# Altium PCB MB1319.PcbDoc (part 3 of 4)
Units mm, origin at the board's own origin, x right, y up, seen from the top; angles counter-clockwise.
Board outline 70 x 82.5 mm, 2 copper layers (Top Layer, Bottom Layer), stack 1.571 mm thick; 252 components, 179 nets, 814 pads, 1000 vias.
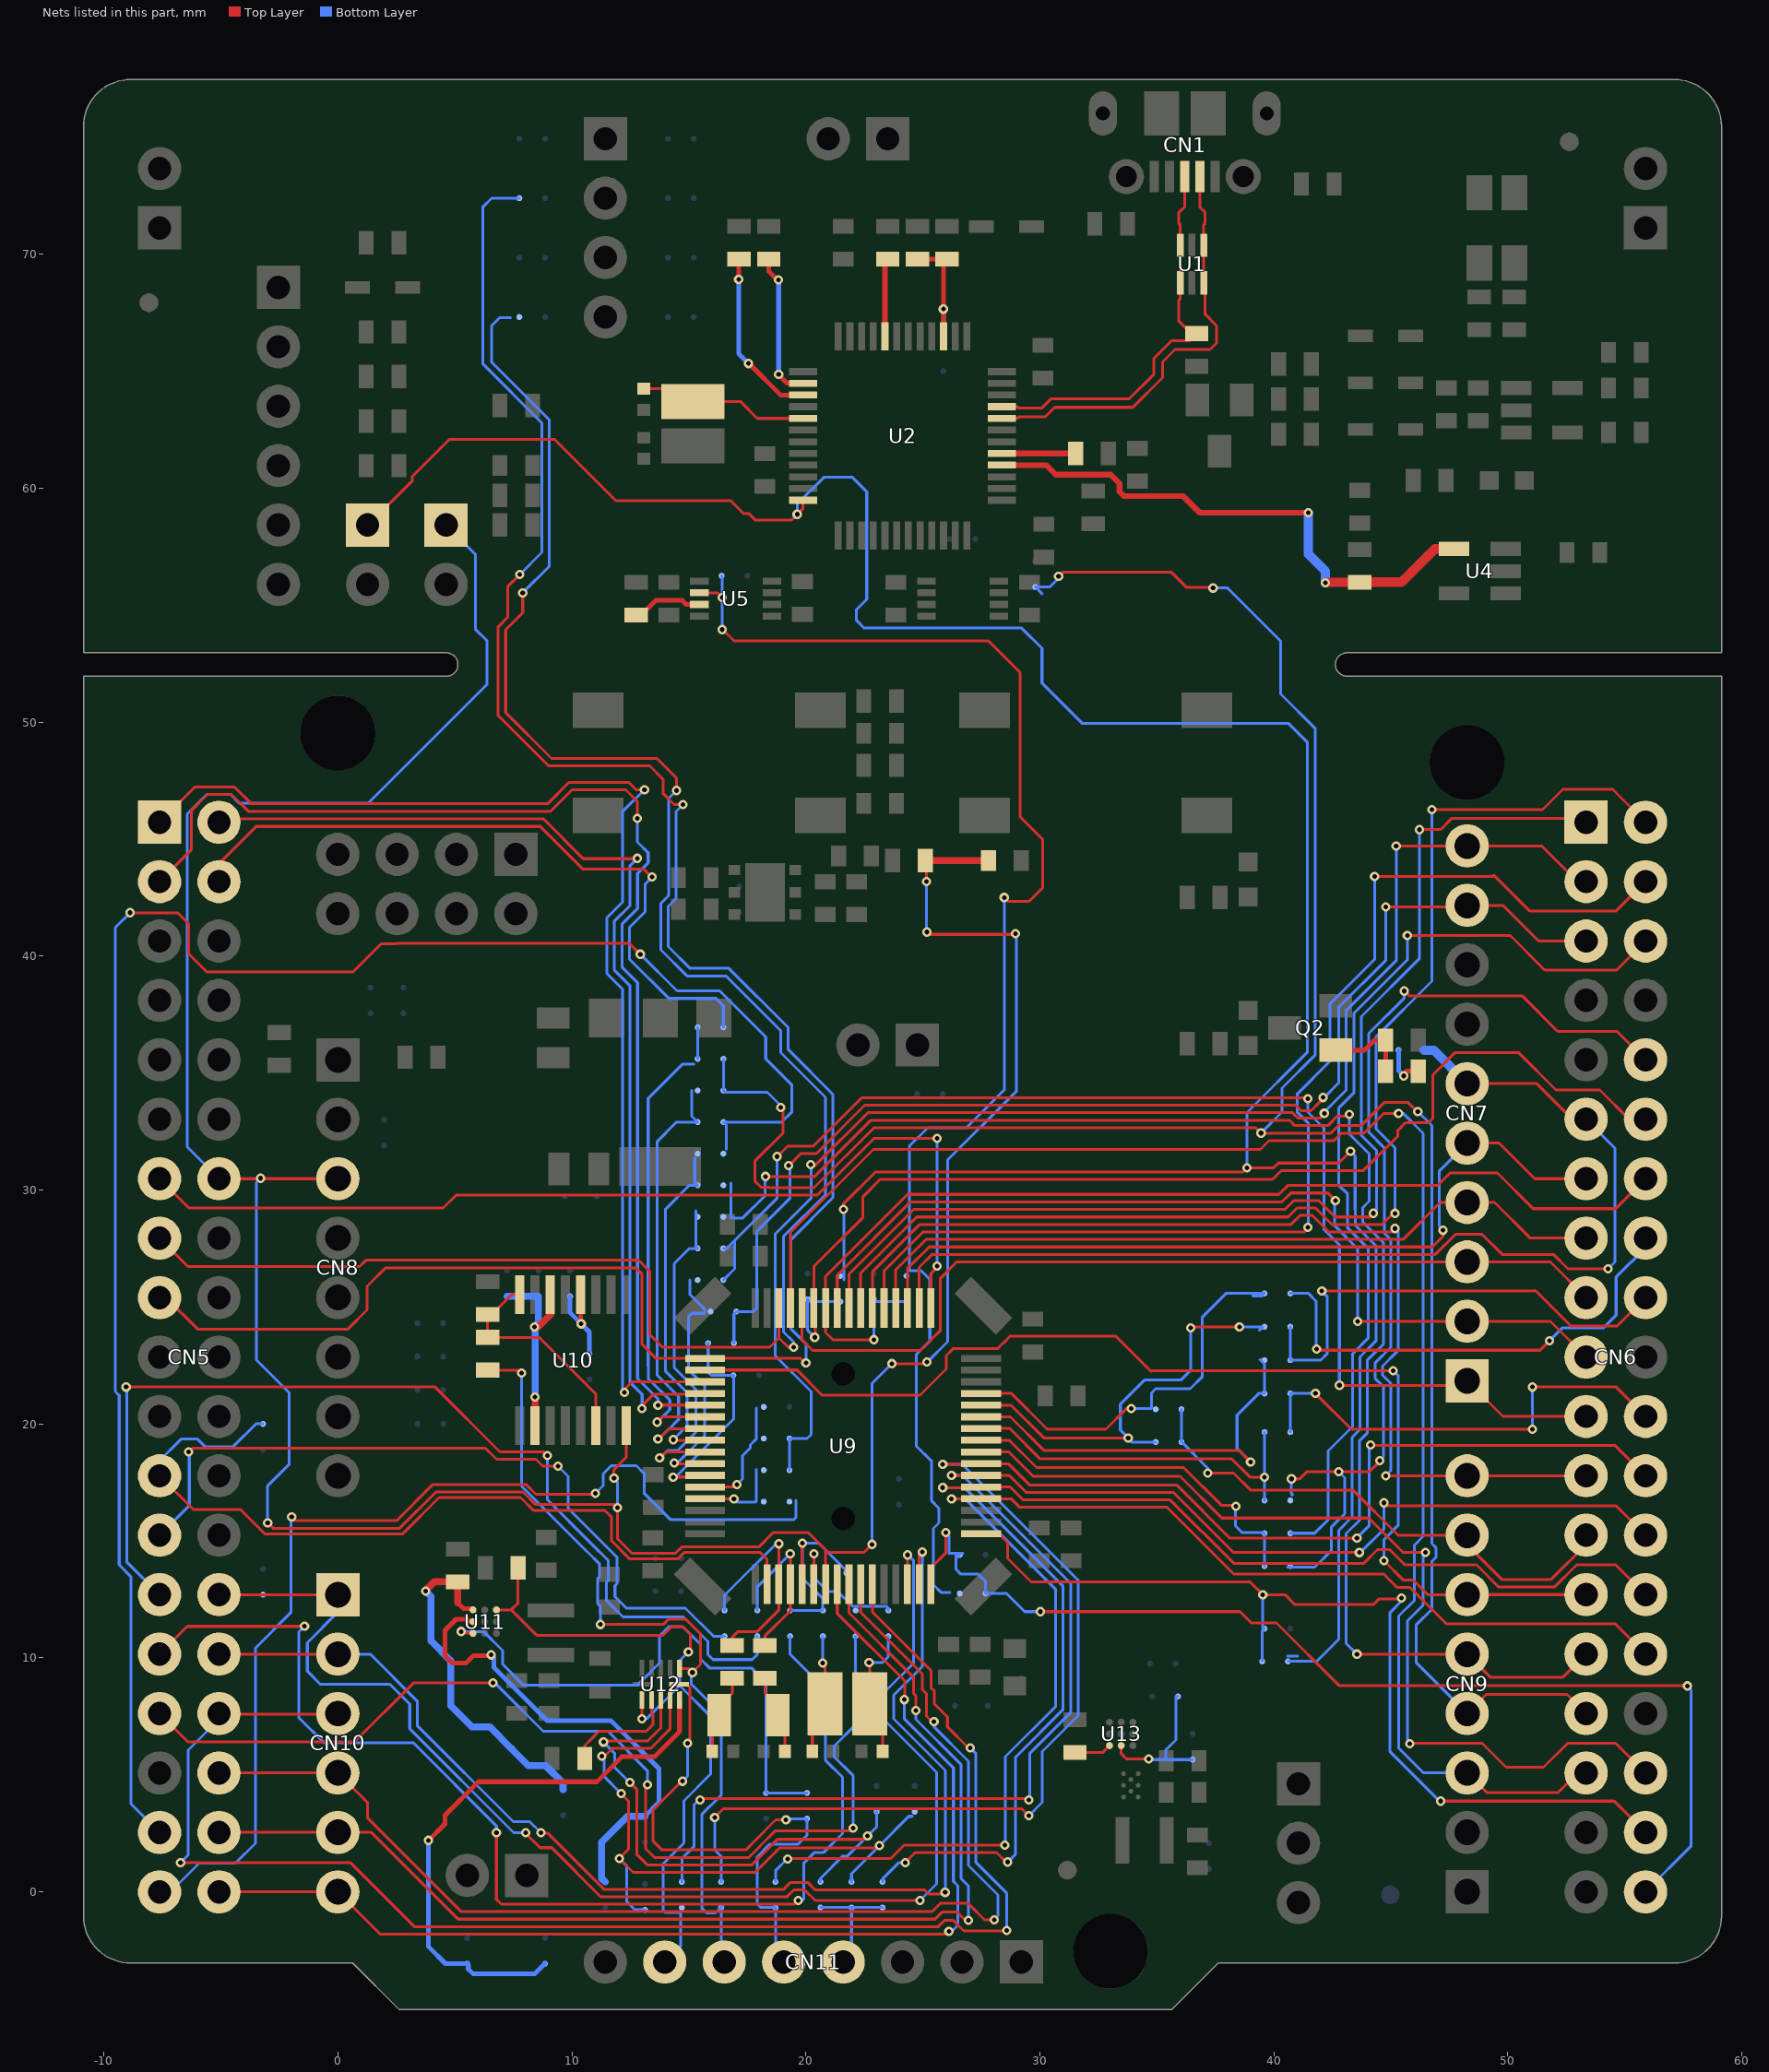
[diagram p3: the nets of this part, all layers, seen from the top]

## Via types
v1: diameter 0.4, hole 0.2, Top Layer to Bottom Layer, tented both sides, 802 vias
v2: diameter 0.6, hole 0.3, Top Layer to Bottom Layer, tented both sides, 198 vias

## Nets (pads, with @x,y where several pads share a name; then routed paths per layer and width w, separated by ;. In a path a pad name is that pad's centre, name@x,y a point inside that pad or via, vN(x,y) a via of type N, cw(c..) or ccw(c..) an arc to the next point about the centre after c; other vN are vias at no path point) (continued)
NetQ2_1: Q2.1 R33.2 R36.2 | length 3.6
  Top Layer w0.2: Q2.1@42.65,35.975 43.875,35.975 44.3,36.4 R33.2@44.775,36.4 R36.2@44.775,35.075
NetR3_2: R3.2 U2.3 | length 7.6
  Top Layer w0.2: v1(17.125,68.925) 17.125,69.765 R3.2@17.145,69.785 ; v1(17.55,65.325) 17.55,65.35 18.92,63.98 U2.3@19.88,63.98
  Bottom Layer w0.2: v1(17.125,68.925) 17.125,65.75 v1(17.55,65.325)
NetR4_2: R4.2 U2.2 | length 6.4
  Top Layer w0.2: R4.2@18.415,69.785 18.415,69.262 18.8,68.877 v1(18.826,68.903) ; v1(18.836,64.864) 18.836,64.85 19.206,64.48 U2.2@19.88,64.48
  Bottom Layer w0.2: v1(18.826,68.903) 18.826,68.929 18.836,68.939 v1(18.836,64.864)
NetR5_2: R5.2 U2.44 | length 3.4
  Top Layer w0.25: U2.44@23.38,66.48 23.38,69.67 R5.2@23.495,69.785
NetR6_1: R6.1 R7.2 SB9.2 U2.39 | length 6.2
  Top Layer w0.2: R6.1@24.765,69.785 R7.2@26.035,69.785 25.875,69.625 v1(25.875,67.65) 25.88,67.645 U2.39@25.88,66.48
  Bottom Layer w0.2: SB9.2@25.875,66.1 v1(25.875,67.65)
NetR19_1: R19.1 U2.29 | length 3.1
  Top Layer w0.25: U2.29@28.38,61.48 31.52,61.48 R19.1@31.525,61.475
NetR26_1: R26.1 U5.7 | length 3
  Top Layer w0.2: R26.1@12.75,54.575 12.961,54.575 13.581,55.195 14.719,55.195 14.889,55.025 U5.7@15.45,55.025
NetR36_1: R36.1 SB17.2 | length 1.9
  Top Layer w0.2: v1(45.55,34.875) 45.55,34.95 45.675,35.075 R36.1@46.175,35.075
  Bottom Layer w0.2: SB17.2@45.325,35.975 45.325,35.1 v1(45.55,34.875)
NetR37_2: R37.2 R38.1 U10.6 U10.16 | length 9.7
  Top Layer w0.12: U10.16@7.775,25.525 7.425,25.525 6.575,24.675 R37.2@6.4,24.675 R38.1@6.4,23.7 6.41,23.69 8.61,23.69 11.025,21.275 U10.6@11.025,19.925
NetR39_2: R39.2 SB83.2 U11.C3 | length 15
  Top Layer w0.2: 5.125,12.35 5.375,12.1 5.725,12.1 U11.C3@5.775,12.05
  Top Layer w0.3: v1(3.75,12.851) 3.75,12.875 4.125,13.25 R39.2@5.125,13.25 5.125,12.35
  Bottom Layer w0.3: v1(3.75,12.851) 3.975,12.626 3.975,10.725 4.825,9.875 4.825,7.95 5.725,7.05 6.495,7.05 7.434,6.111 7.434,6.109 8.143,5.4 8.875,5.4 9.625,4.65 SB83.2@9.625,4.375
NetR41_1: R41.1 SB71.2 U9.4 | length 7.4
  Top Layer w0.12: R41.1@18.25,10.525 18.25,10.925 19.34,12.015 U9.4@19.34,13.15 19.34,14.44 v1(19.33,14.45)
  Bottom Layer w0.12: SB71.2@17.925,12.025 17.925,13.045 v1(19.33,14.45)
NetR42_1: R42.1 SB72.2 U9.3 | length 9.5
  Top Layer w0.12: R42.1@16.85,10.525 16.85,10.874 17.101,11.125 17.925,11.125 18.84,12.04 U9.3@18.84,13.15 18.84,14.865 v1(18.85,14.875)
  Bottom Layer w0.12: SB72.2@16.525,12.025 16.525,12.675 18.725,14.875 v1(18.85,14.875)
NetR43_1: R43.1 U13.C3 | length 1.6
  Top Layer w0.12: R43.1@31.5,5.95 32.675,5.95 U13.C3@32.975,6.25
NetR44_2: R44.2 U12.8 | length 4.9
  Top Layer w0.12: R44.2@10.55,5.7 10.55,6.25 10.891,6.591 11.16,6.86 13.185,6.86 13.46,7.135 13.46,7.591 13.4,7.651 U12.8@13.4,8.2
NetSB16_1: SB16.1 SB18.1 U9.54 | length 20.5
  Top Layer w0.127: v1(13.65,20.075) 13.875,20.3 U9.54@15.69,20.3
  Bottom Layer w0.12: 13.262,22.475 13.262,21.941 13.775,21.427 ; SB18.1@15.375,35.6 SB16.1@15.375,36.95
  Bottom Layer w0.127: 13.262,22.475 13.262,33.912 14.725,35.375 15.225,35.375 ; v1(13.65,20.075) 14.186,20.611 14.186,21.016 13.775,21.427
NetSB19_1: SB19.1 SB22.1 U9.55 | length 19.2
  Top Layer w0.12: v1(13.675,19.35) 13.704,19.35 14.139,19.785 15.675,19.785 U9.55@15.69,19.8
  Bottom Layer w0.12: v1(13.675,19.35) 13.704,19.35 14.139,19.785 14.155,19.785 14.56,20.19 14.56,21.17 13.635,22.095 13.635,32.06 14.475,32.9 SB22.1@15.375,32.9 15.125,33.15 15.125,34.25
NetSB23_1: SB23.1 SB26.1 U9.56 | length 14.9
  Top Layer w0.12: v1(14.33,19.325) 14.355,19.3 U9.56@15.69,19.3
  Bottom Layer w0.12: v1(14.33,19.325) 14.93,19.925 14.93,21.324 14.005,22.248 14.005,29.18 15.025,30.2 SB26.1@15.375,30.2 15.25,30.325 15.25,31.375
NetSB27_1: SB27.1 SB28.1 U9.57 | length 14.6
  Top Layer w0.12: v1(13.751,18.551) 13.751,18.501 14.05,18.8 U9.57@15.69,18.8
  Bottom Layer w0.12: v1(13.751,18.551) 13.75,18.525 14.09,18.865 14.521,18.865 15.3,19.644 15.3,21.477 14.375,22.402 14.375,26.85 15.025,27.5 SB28.1@15.375,27.5 15.3,27.575 15.3,29.1
NetSB29_2: SB29.2 SB42.2 U10.12 | length 4.1
  Top Layer w0.127: v1@10.375,24.35 10.45,24.275 v1(10.4,24.275)
  Top Layer w0.2: v1@10.375,24.35 U10.12@10.375,25.525
  Bottom Layer w0.2: SB29.2@9.925,25.45 9.925,24.75 v1(10.4,24.275) 10.75,23.925 SB42.2@10.75,23
NetSB30_2: SB30.2 SB31.2 U10.2 U10.14 | length 8.7
  Top Layer w0.3: v1(8.4,24.15) 8.57,24.15 9.1,24.68 9.1,25.5 U10.14@9.075,25.525 ; U10.2@8.425,19.925 v1(8.425,21.15)
  Bottom Layer w0.3: SB31.2@7.225,25.45 SB30.2@8.575,25.45 8.575,24.325 v1(8.4,24.15) 8.425,24.125 v1(8.425,21.15)
NetSB36_1: SB36.1 SB38.1 U9.58 | length 11
  Top Layer w0.12: v1(14.376,18.326) 14.35,18.3 14.35,18.275 14.375,18.3 U9.58@15.69,18.3
  Bottom Layer w0.12: v1(14.376,18.326) 14.505,18.326 15.67,19.491 15.67,21.63 14.975,22.325 14.975,24.575 15.125,24.725 15.675,24.725 15.675,24.9 15.05,25.525 15.05,26.15
NetSB37_1: SB37.1 SB49.1 U9.29 | length 17.6
  Top Layer w0.12: U9.29@27.49,21.3 28.786,21.3 30.316,19.77 32.82,19.77 33.7,20.65 v1(33.9,20.65)
  Bottom Layer w0.12: v1(33.9,20.65) 34.775,20.65 34.775,21.325 34.95,21.5 36.425,21.5 36.945,22.02 36.945,24.57 37.95,25.575 SB37.1@39.6,25.575 39.5,25.475 39.1,25.475
NetSB40_1: SB40.1 SB54.1 U9.28 | length 18.5
  Top Layer w0.12: U9.28@27.49,20.8 28.763,20.8 30.163,19.4 v1(33.775,19.4) ; v1(36.45,24.1) 36.501,24.151 v1(38.527,24.151)
  Bottom Layer w0.12: SB54.1@34.95,19.225 33.925,19.225 33.75,19.4 v1(33.775,19.4) 33.44,19.735 33.44,20.841 34.469,21.87 36.02,21.87 36.45,22.3 v1(36.45,24.1) ; v1(38.527,24.151) 38.526,24.15 39.525,24.15 39.375,24
NetSB41_2: SB41.2 SB45.1 U9.59 | length 9.3
  Top Layer w0.127: v1(14.326,17.726) 15.616,17.726 U9.59@15.69,17.8
  Bottom Layer w0.127: v1(14.326,17.726) 14.433,17.726 16.916,20.209 16.916,22.059 SB45.1@16.9,22.075 15.95,22.075 15.825,22.2 SB41.2@15.825,23.45
NetSB44_1: SB44.1 SB47.1 U9.27 | length 17.6
  Top Layer w0.12: U9.27@27.49,20.3 28.74,20.3 30.17,18.87 38.505,18.87 v1(39,18.375)
  Bottom Layer w0.12: v1(39,18.375) 38.425,18.95 38.425,20.375 39.35,21.3 SB47.1@39.6,21.3 39.6,22.55 39.4,22.75
NetSB48_1: SB48.1 SB53.1 U9.60 | length 5
  Top Layer w0.12: U9.60@15.69,17.3 16.95,17.3 v1(17.051,17.401)
  Bottom Layer w0.12: v1(17.051,17.401) 17.29,17.64 17.29,18.64 17.625,18.975 17.625,19.1 17.875,19.35 17.875,20.675
NetSB52_1: SB52.1 SB57.1 U9.26 | length 15.9
  Top Layer w0.12: U9.26@27.49,19.8 28.716,19.8 30.016,18.5 38.2,18.5 38.975,17.725 v1(39.6,17.725)
  Bottom Layer w0.12: SB57.1@39.6,16.725 v1(39.6,17.725) SB52.1@39.6,19.65
NetSB55_1: SB55.1 SB58.1 U9.61 | length 3.6
  Top Layer w0.12: U9.61@15.69,16.8 v1(16.925,16.8)
  Bottom Layer w0.12: v1(16.925,16.8) 17.075,16.65 17.85,16.65 17.875,16.675 17.875,18.05
NetSB59_1: SB59.1 SB63.1 U9.25 | length 15.7
  Top Layer w0.12: U9.25@27.49,19.3 28.693,19.3 29.863,18.13 36.145,18.13 37.75,16.525 38.375,16.525 38.377,16.523 v1(38.377,16.476)
  Bottom Layer w0.12: v1(38.377,16.476) 38.351,16.476 38.351,15.649 38.65,15.35 39.575,15.35 SB59.1@39.6,15.325 SB63.1@39.6,13.925
NetSB64_2: SB64.2 SB69.2 SB70.2 U9.5 | length 8.9
  Top Layer w0.12: U9.5@19.84,13.15 19.84,14.89 v1(19.85,14.9)
  Bottom Layer w0.12: SB70.2@19.325,12.025 SB69.2@20.725,12.025 20.725,12.527 19.85,13.402 v1(19.85,14.9) 19.86,14.91 20.541,14.91 21.725,13.726 SB64.2@21.725,13.625
NetSB67_2: SB67.2 SB68.2 U9.6 | length 6.1
  Top Layer w0.12: U9.6@20.34,13.15 20.34,14.44 v1(20.35,14.45)
  Bottom Layer w0.12: v1(20.35,14.45) 20.35,13.425 20.94,12.835 21.365,12.835 22,12.2 23.45,12.2 23.525,12.125 SB67.2@23.525,12.025
NetSB79_2: SB79.2 SB80.2 U13.B3 | length 6.4
  Top Layer w0.12: U13.B3@33.475,6.25 33.475,5.9 33.7,5.675 v1(34.65,5.675)
  Bottom Layer w0.12: v1@34.675,5.675 34.7,5.65 35.375,5.65 ; SB79.2@35.9,8.35 35.815,8.35 35.815,6.489 35.541,6.215 35.375,6.05 35.375,5.65 ; SB80.2@36.525,5.65 35.375,5.65
NetSB81_2: SB81.2 SB91.2 U12.9 | length 24
  Top Layer w0.12: v1(11.351,6.4) 11.4,6.45 13.242,6.45 13.8,7.007 U12.9@13.8,8.2 ; v1(12.475,4.674) 12.785,4.364 12.785,1.59 13.225,1.15 17.697,1.15 18.4,1.853 18.4,1.859 18.781,2.24 22.49,2.24 v1(22.638,2.388)
  Bottom Layer w0.12: v1(11.351,6.4) 11.825,5.926 11.825,5.324 v1(12.475,4.674) ; SB91.2@20.625,0.425 20.625,0.575 21.575,1.525 21.775,1.525 v1(22.638,2.388) 23.025,2.775 SB81.2@23.025,3.425
NetSB82_2: SB82.2 SB90.2 SB94.2 U12.10 | length 28.4
  Top Layer w0.12: v1(11.276,5.8) 11.401,5.8 11.73,6.13 13.375,6.13 14.19,6.945 U12.10@14.19,8.2 ; v1(12.101,4.2) 12.415,3.886 12.415,1.815 v1(12.025,1.425) 12.62,0.83 17.83,0.83 18.72,1.72 18.72,1.727 18.863,1.87 23.044,1.87 v1(23.149,1.975)
  Bottom Layer w0.12: v1(11.276,5.8) 11.385,5.691 11.385,4.916 v1(12.101,4.2) ; v1(12.025,1.425) 12.35,1.1 12.35,-0.425 12.7,-0.775 SB94.2@13.125,-0.775 ; SB90.2@21.95,0.425 21.95,0.776 v1(23.149,1.975) 24.399,3.225 24.55,3.225
NetSB84_2: SB84.2 SB85.2 U11.A3 | length 24.4
  Top Layer w0.12: v1(5.275,11.125) 5.35,11.05 U11.A3@5.775,11.05
  Bottom Layer w0.12: v1(5.275,11.125) 6.228,11.125 7.04,10.313 7.04,9.726 7.941,8.825 12.791,8.825 13.74,9.774 13.74,10.932 14.143,11.335 14.732,11.335 15.495,10.572 15.495,9.955 15.895,9.555 17.695,9.555 18.3,8.95 SB85.2@18.3,4.225 SB84.2@20.05,4.225
NetSB86_2: SB86.2 SB95.2 U11.B3 | length 20.6
  Top Layer w0.2: U11.B3@5.775,11.55 5.639,11.55 5.539,11.65 5.05,11.65 4.575,11.175 4.575,10.085 4.875,9.785 5.484,9.785 5.799,10.1 6.525,10.1 v1(6.55,10.125)
  Bottom Layer w0.2: v1(6.55,10.125) 6.675,10 6.675,9.582 8.937,7.32 11.665,7.32 13.725,5.261 13.725,3.825 SB86.2@13.125,3.225
  Bottom Layer w0.3: SB95.2@11.425,0.425 11.275,0.575 11.275,2.125 12.375,3.225 SB86.2@13.125,3.225
NetSB96_2: SB96.2 SB97.2 U12.11 | length 24.5
  Top Layer w0.2: v1(3.874,2.199) 4.575,2.899 4.575,3.275 6.004,4.704 11.067,4.704 12.133,5.77 13.524,5.77 14.6,6.846 U12.11@14.6,8.2
  Bottom Layer w0.2: v1(3.874,2.199) 3.874,-2.349 4.6,-3.075 SB96.2@5.525,-3.075 5.575,-3.125 5.575,-3.3 5.775,-3.5 8.425,-3.5 SB97.2@8.85,-3.075
NRST: C23.2 CN5.14 CN8.3 JP4.1 R31.1 U9.7 U10.8 | length 133.8
  Top Layer w0.12: CN5.14@-5.08,30.48 v1@-3.32,30.48 ; v1(-3.3,30.5) v1@-3.32,30.48 ; v1(-3,15.775) -2.765,15.54 2.64,15.54 4.19,17.09 7.91,17.09 8.435,16.565 11.815,16.565 v1@11.95,16.43 ; CN8.3@0,30.48 v1@-3.32,30.48 ; v1(11.8,17.675) 11.8,18.05 12.325,18.575 U10.8@12.325,19.925 ; v1@11.94,16.51 11.94,15.099 12.574,14.465 14.426,14.465 14.701,14.74 17.99,14.74 18.61,15.36 20.091,15.36 20.84,14.611 ; U9.7@20.84,13.15 20.84,14.611 ; v1(22.825,14.85) 22.49,14.515 20.936,14.515 20.84,14.611 ; v1(23.675,22.575) 25.1,22.575 v1(25.176,22.651) ; R31.1@25.1,44.075 25.15,44.025 v1(25.15,43.175) ; v1(25.175,41.025) 25.275,40.925 28.95,40.925 v1(28.95,40.95)
  Top Layer w0.3: R31.1@25.1,44.075 C23.2@27.8,44.075
  Bottom Layer w0.12: CN5.14@-5.08,30.48 -6.435,31.835 -6.435,46.065 -5.595,46.905 -4.589,46.905 -4.224,46.54 1.307,46.54 6.38,51.613 6.38,53.47 5.875,53.975 5.875,57.17 JP4.1@4.625,58.42 ; v1(-3.3,30.5) -3.48,30.32 -3.48,22.733 -2.09,21.343 -2.09,18.26 -3,17.35 v1(-3,15.775) ; v1(11.8,17.675) 11.95,17.525 v1(11.95,16.425) ; v1(22.825,14.85) 22.825,21.725 v1(23.675,22.575) ; v1(25.15,43.175) 25.15,41.05 v1(25.175,41.025) ; v1(25.176,22.651) 25.199,22.651 26.061,23.513 26.061,31.286 29,34.225 29,41 v1(28.95,40.95)
OSC32_IN: C45.1 R42.2 X3.1 | length 3.5
  Top Layer w0.12: C45.1@16,6 16,7.25 X3.1@16.3,7.55 16.3,7.925 16.85,8.475 R42.2@16.85,9.125
OSC32_OUT: C46.1 R41.2 X3.2 | length 3.5
  Top Layer w0.12: R41.2@18.25,9.125 18.25,8.525 18.8,7.975 X3.2@18.8,7.55 19.1,7.25 C46.1@19.1,6
OSC_IN: C47.2 SB69.1 X2.2 | length 4.4
  Top Layer w0.12: C47.2@20.275,6 X2.2@20.275,7.475 ; v1(20.725,9.775) 20.825,9.675 X2.2@20.825,8.025
  Bottom Layer w0.12: v1(20.725,9.775) SB69.1@20.725,10.925
OSC_OUT: C48.2 SB67.1 X2.1 | length 5.8
  Top Layer w0.12: v1(22.7,9.8) 22.725,9.775 X2.1@22.725,8.025 23.275,7.475 C48.2@23.275,6
  Bottom Layer w0.12: v1(22.7,9.8) 23.275,9.8 23.525,10.05 SB67.1@23.525,10.925
PA0: CN5.28 CN10.1 SB62.2 U9.14 | length 59.8
  Top Layer w0.12: CN5.28@-5.08,12.7 CN10.1@0,12.7 ; v1(8.024,2.525) 8.024,2.501 8.64,1.885 9.14,1.885 11.235,-0.21 19.216,-0.21 19.216,-0.184 19.485,0.085 19.94,0.085 20.4,-0.375 v1(24.876,-0.375) ; U9.14@24.34,13.15 24.34,14.39 v1(24.35,14.4)
  Bottom Layer w0.12: CN5.28@-5.08,12.7 SB62.2@-3.2,12.7 ; CN10.1@0,12.7 0,11.95 -1.305,10.645 -1.305,9.43 -0.75,8.875 2.218,8.875 3.07,8.023 3.07,6.973 7.518,2.525 v1(8.024,2.525) ; v1(24.35,14.4) 24.605,14.145 24.605,9.781 23.381,8.557 23.381,7.314 25.59,5.105 25.59,0.339 v1(24.876,-0.375)
PA1: CN5.30 CN10.2 U9.15 | length 53.6
  Top Layer w0.12: CN5.30@-5.08,10.16 CN10.2@0,10.16 ; v1(8.675,2.525) 8.7,2.5 8.978,2.5 11.368,0.11 19.058,0.11 19.353,0.405 20.073,0.405 20.393,0.085 25.067,0.085 25.25,-0.099 25.951,-0.099 v1(25.951,-0.025) ; U9.15@24.84,13.15 24.84,14.385 v1(24.975,14.52)
  Bottom Layer w0.12: CN10.2@0,10.16 1.385,10.16 3.39,8.155 3.39,7.105 7.495,3 8.2,3 v1(8.675,2.525) ; v1(24.975,14.52) 24.975,9.628 23.751,8.404 23.751,7.396 25.96,5.187 25.96,-0.016 v1(25.951,-0.025)
PA2: CN6.38 SB60.1 SB66.2 U9.16 | length 48.1
  Top Layer w0.12: U9.16@25.34,13.15 25.34,13.84 25.975,14.475 v1(25.975,15.35) ; v1(30.025,11.975) 38.553,11.975 39.033,11.495 40.11,11.495 42.8,8.805 57.655,8.805 57.675,8.825 v1(57.675,8.8)
  Bottom Layer w0.12: v1(25.975,15.35) 26.125,15.2 26.125,14.475 26.412,14.475 ; 26.475,14.3 SB60.1@26.575,14.4 ; 26.7,14.475 26.412,14.475 ; v1(30.025,11.975) 29.35,11.975 28.575,12.75 SB66.2@27.675,12.75 27.675,13.275 27.375,13.575 26.625,13.575 26.412,13.787 26.412,14.475 ; CN6.38@55.88,0 57.82,1.94 57.82,8.655 v1(57.675,8.8)
PA3: CN6.36 SB73.1 SB75.2 U9.17 | length 41.8
  Top Layer w0.12: U9.17@27.49,15.3 28.25,15.3 28.625,14.925 28.625,14.25 29.625,13.25 38.978,13.25 v1(39.527,12.701) 40.474,12.701 40.9,12.275 44.25,12.275 44.5,12.525 45.45,12.525 v1(45.45,12.551) ; v1(47.125,3.875) 54.545,3.875 CN6.36@55.88,2.54
  Bottom Layer w0.12: SB75.2@39.5,9.85 39.5,11.15 SB73.1@39.6,11.25 39.525,11.325 39.525,12.699 v1(39.527,12.701) ; v1(45.45,12.551) 45.45,12.423 44.965,11.938 44.965,5.986 47.076,3.875 v1(47.125,3.875)
PA4: CN6.30 SB92.2 U9.20 | length 61.1
  Top Layer w0.12: v1(19.226,1.4) 19.251,1.425 23.625,1.425 24.195,1.995 28.496,1.995 v1(28.501,2) ; v1(26.225,16.8) U9.20@27.49,16.8 28.772,16.8 29.142,16.43 35.441,16.43 38.296,13.575 44.7,13.575 45.264,13.011 45.814,13.011 47.375,11.45 54.59,11.45 CN6.30@55.88,10.16
  Bottom Layer w0.12: SB92.2@18.7,0.425 18.7,0.9 19.2,1.4 v1(19.226,1.4) ; v1(26.225,16.8) 26.797,16.8 30.675,12.922 30.675,7.925 28.526,5.776 28.526,1.975 v1(28.501,2)
PA5: CN6.28 SB89.2 U9.21 | length 59
  Top Layer w0.12: v1(24.25,1.25) 24.675,1.675 28.15,1.675 28.575,1.25 28.601,1.25 v1(28.626,1.275) ; v1(25.85,17.275) 27.465,17.275 U9.21@27.49,17.3 28.741,17.3 29.291,16.75 35.573,16.75 38.283,14.04 43.841,14.04 44.426,14.625 44.951,14.625 45.601,13.975 48.661,13.975 49.612,13.023 51.988,13.023 52.939,13.975 54.605,13.975 CN6.28@55.88,12.7
  Bottom Layer w0.12: SB89.2@23.275,0.425 23.275,0.55 23.975,1.25 v1(24.25,1.25) ; v1(25.85,17.275) 26.775,17.275 30.995,13.055 30.995,7.792 28.961,5.759 28.961,1.61 v1(28.626,1.275)
PA6: CN6.26 SB93.2 U9.22 | length 68.2
  Top Layer w0.12: v1(15.476,3.925) 15.526,3.975 29.477,3.975 v1(29.526,3.925) ; v1(26.225,17.8) U9.22@27.49,17.8 28.694,17.8 29.424,17.07 35.706,17.07 38.276,14.5 v1(43.65,14.5) ; v1(44.7,16.625) 44.825,16.5 54.62,16.5 CN6.26@55.88,15.24
  Bottom Layer w0.12: SB93.2@14.7,0.425 14.7,1.425 15.225,1.95 15.225,3.725 15.45,3.95 v1@15.475,3.925 ; v1(26.225,17.8) 26.703,17.8 31.315,13.188 31.315,7.66 29.575,5.92 29.575,3.877 v1(29.526,3.925) ; v1(43.65,14.5) 43.692,14.5 44.7,15.508 v1(44.7,16.625)
PA7: CN6.24 SB88.2 U9.23 | length 70.9
  Top Layer w0.12: v1(16.1,3.175) 16.475,3.55 29.225,3.55 v1(29.525,3.25) ; v1(25.85,18.275) 27.465,18.275 U9.23@27.49,18.3 28.647,18.3 29.557,17.39 35.838,17.39 38.103,15.125 v1(43.55,15.125) ; v1(44.125,19.1) 44.15,19.075 54.585,19.075 CN6.24@55.88,17.78
  Bottom Layer w0.12: v1(16.1,3.175) 16.125,3.2 16.125,3 16.115,2.99 16.115,1.78 16.375,1.52 SB88.2@16.375,0.425 ; v1(25.85,18.275) 26.68,18.275 31.635,13.32 31.635,7.527 30.1,5.992 30.1,3.825 v1(29.525,3.25) ; v1(43.55,15.125) 44.067,15.642 44.067,19.042 v1(44.125,19.1)
PA8: CN6.19 CN7.2 U9.41 | length 40.3
  Top Layer w0.12: U9.41@21.34,24.95 21.34,26.352 24.478,29.49 40.346,29.49 40.726,29.87 42.305,29.87 v1(42.625,29.55) ; v1(43.575,24.375) 43.584,24.384 CN7.2@48.26,24.384 51.816,24.384 CN6.19@53.34,22.86
  Bottom Layer w0.12: v1(42.625,29.55) 42.6,29.525 42.6,28.468 43.575,27.493 v1(43.575,24.375)
PA9: CN6.14 SB34.2 SB35.1 U9.42 | length 45.8
  Top Layer w0.12: v1(22.9,23.6) 21.15,23.6 20.84,23.91 U9.42@20.84,24.95 20.84,26.304 24.346,29.81 40.213,29.81 40.593,30.19 46.99,30.19 47.525,30.725 49.55,30.725 51.075,29.2 54.6,29.2 CN6.14@55.88,30.48
  Bottom Layer w0.12: v1(22.9,23.6) SB35.1@22.9,25.325 23,25.225 SB34.2@24.3,25.225
PA10: CN6.12 SB32.2 SB33.1 U9.43 | length 48.6
  Top Layer w0.12: v1(20.376,23.701) 20.4,23.725 20.4,24.89 U9.43@20.34,24.95 20.34,26.727 22.44,28.827 22.44,29.714 23.176,30.45 39.948,30.45 40.328,30.83 43.827,30.83 45.3,32.303 45.3,32.549 45.623,32.873 46.599,32.873 46.788,33.062 46.788,34.913 47.75,35.875 50.45,35.875 52.05,34.275 53.925,34.275 55.18,33.02 CN6.12@55.88,33.02
  Bottom Layer w0.12: v1@20.325,23.65 v1(20.376,23.701) 20.075,24.002 SB33.1@20.075,25.325 20.175,25.225 SB32.2@21.475,25.225
PA11: CN6.17 CN7.3 U9.44 | length 38.6
  Top Layer w0.12: U9.44@19.84,24.95 19.84,23.587 20.287,23.14 24.89,23.14 25.59,23.84 25.598,23.84 25.75,23.992 25.75,26.225 26.449,26.924 CN7.3@48.26,26.924 51.816,26.924 CN6.17@53.34,25.4
PA12: CN6.33 CN9.3 U9.45 | length 68.6
  Top Layer w0.12: U9.45@19.34,24.95 19.34,28.184 22.886,31.73 39.418,31.73 39.798,32.11 42.567,32.11 42.887,32.43 43.854,32.43 44.699,33.275 v1(45.325,33.275) ; CN9.3@48.26,5.08 49.095,4.245 52.15,4.245 52.985,5.08 CN6.33@53.34,5.08
  Bottom Layer w0.12: v1(45.325,33.275) 45.526,33.275 46.38,32.421 46.38,15.195 46.01,14.825 46.01,12.46 45.335,11.785 45.335,6.139 46.394,5.08 CN9.3@48.26,5.08
PA13: CN5.15 SB8.1 U9.46 | length 89.6
  Top Layer w0.12: CN5.15@-7.62,27.94 -6.405,26.725 0.934,26.725 1.204,26.995 12.858,26.995 13.32,26.533 13.32,23.83 13.875,23.275 18.45,23.275 18.85,23.675 ; v1(7.9,55.525) 7.9,54.672 7.17,53.942 7.17,50.408 9.133,48.445 13.633,48.445 14.475,47.603 v1(14.475,47.075) ; U9.46@18.84,24.95 18.85,24.94 18.85,23.675 ; v1(19.475,23.275) 19.25,23.275 18.85,23.675
  Bottom Layer w0.12: 7.375,67.275 6.9,67.275 6.575,66.95 6.575,65.375 9.04,62.91 9.04,56.665 v1(7.9,55.525) ; v1(14.475,47.075) 14.135,46.735 14.135,42.584 13.8,42.249 13.8,40.268 14.918,39.15 16.577,39.15 18.925,36.802 18.925,35.869 20.835,33.959 20.835,29.802 19.045,28.012 19.045,23.929 19.475,23.499 v1(19.475,23.275)
PA14: CN5.17 SB4.1 U9.49 | length 97.4
  Top Layer w0.12: CN5.17@-7.62,25.4 -7.35,25.4 -6,24.05 0.425,24.05 1.25,24.875 1.25,25.875 2.05,26.675 12.725,26.675 13,26.4 13,23.4 13.6,22.8 U9.49@15.69,22.8 19.775,22.8 19.975,22.6 v1(20.001,22.601) v1(20.001,22.601) ; v1(7.775,56.305) 7.25,55.78 7.25,54.475 6.85,54.075 6.85,50.275 9,48.125 13.328,48.125 13.895,47.558 13.895,46.955 14.375,46.475 v1(14.75,46.475)
  Bottom Layer w0.12: SB4.1@7.755,72.39 6.565,72.39 6.2,72.025 6.2,65.297 8.72,62.777 8.72,57.25 v1(7.775,56.305) ; v1(14.75,46.475) 14.455,46.18 14.455,42.452 14.12,42.117 14.12,40.4 15.05,39.47 16.71,39.47 19.245,36.935 19.245,36.001 21.155,34.091 21.155,29.67 19.365,27.88 19.365,24.062 20.001,23.426 v1(20.001,22.601)
PA15: CN6.27 CN9.6 U9.50 | length 49.6
  Top Layer w0.12: 22.05,21.225 24.875,21.225 26,22.35 26,22.925 26.285,23.21 28.185,23.21 28.427,23.451 ; v1(44.7,14.15) 45.519,13.331 45.947,13.331 46.578,12.7 CN9.6@48.26,12.7
  Top Layer w0.127: U9.50@15.69,22.3 19.625,22.3 20.7,21.225 22.05,21.225 ; 28.427,23.451 28.725,23.75 33.25,23.75 34.75,22.25 34.775,22.275 v1(45.1,22.275) ; CN9.6@48.26,12.7 CN6.27@53.34,12.7
  Bottom Layer w0.12: v1(44.7,14.15) 44.7,15.055 45.32,15.675 45.32,22.055 v1(45.1,22.275)
PB0: CN6.10 SB57.2 SB63.2 | length 43.9
  Top Layer w0.12: v1(40.75,17.65) 41.1,17.65 41.4,17.95 v1(42.775,17.95) 44.075,17.95 v1@44.55,18.425 ; v1(44.527,18.426) v1@44.549,18.426 ; v1(45.575,38.5) 45.775,38.3 50.6,38.3 52.125,36.775 54.665,36.775 CN6.10@55.88,35.56 ; v1@44.549,18.426 v1@44.55,18.425
  Bottom Layer w0.12: 40.575,13.875 41.75,13.875 42.45,14.575 42.45,15.581 43.025,16.156 43.025,17.7 v1(42.775,17.95) ; v1(40.75,17.65) 40.75,17.025 40.8,16.975 40.775,16.95 ; v1(44.527,18.426) 44.525,18.428 44.68,18.583 44.68,21.592 44.32,21.952 44.32,22.598 45,23.278 45,27.878 44.715,28.163 44.715,31.805 44.055,32.465 44.055,36.683 45.575,38.203 v1(45.575,38.5)
PB1: CN6.22 SB47.2 SB52.2 | length 19.8
  Top Layer w0.12: v1(41.775,21.3) 43.3,19.775 v1(51.05,19.775) ; v1(51.05,21.575) 54.625,21.575 CN6.22@55.88,20.32
  Bottom Layer w0.12: SB52.2@40.7,19.65 SB47.2@40.7,21.3 v1(41.775,21.3) ; v1(51.05,19.775) v1(51.05,21.575)
PB2: CN6.18 SB40.2 SB44.2 | length 20.9
  Top Layer w0.12: v1(42.05,25.675) 51.15,25.675 51.175,25.7 52.7,24.175 54.655,24.175 CN6.18@55.88,25.4
  Bottom Layer w0.12: SB40.2@40.7,24.15 SB44.2@40.7,22.725 42.001,22.725 42.287,23.011 42.287,25.438 v1(42.05,25.675)
PB3: CN6.31 CN9.4 SB11.2 SB18.2 SB19.2 | length 106.5
  Top Layer w0.12: v1(18.926,33.527) 19.025,33.428 19.025,32.434 17.816,31.225 17.816,30.386 18.085,30.116 18.404,30.116 18.425,30.095 20.346,30.095 22.913,32.662 39.218,32.662 v1(39.45,32.43) 42.435,32.43 42.755,32.75 43.722,32.75 44.707,33.735 45.74,33.735 46.15,33.325 46.152,33.327 v1(46.152,33.352) ; v1(30.8,56.225) 30.975,56.4 35.625,56.4 36.275,55.75 37.38,55.75 v1(37.402,55.728) ; CN9.4@48.26,7.62 49.075,8.435 52.525,8.435 CN6.31@53.34,7.62
  Bottom Layer w0.12: SB18.2@16.475,35.6 SB19.2@16.475,34.25 16.55,34.175 18.353,34.175 19.002,33.527 v1(18.926,33.527) ; 30.09,55.485 SB11.2@29.8,55.775 30.425,55.775 30.875,56.225 v1(30.8,56.225) ; v1(37.402,55.728) 38.022,55.728 38.912,54.838 38.912,54.834 39.784,53.962 39.788,53.962 40.291,53.459 40.291,51.205 41.76,49.736 41.76,35.766 40.35,34.356 40.35,33.33 v1(39.45,32.43) ; v1(46.152,33.352) 46.75,32.754 46.75,14.879 46.937,14.691 46.937,14.31 46.75,14.123 46.75,12.075 46.075,11.4 46.075,9.805 CN9.4@48.26,7.62
PB4: CN5.35 SB22.2 SB23.2 | length 79.5
  Top Layer w0.12: v1(-8.875,41.85) -6.85,41.85 -6.375,41.375 -6.375,40.1 -5.59,39.315 0.64,39.315 1.85,40.525 2.483,40.525 2.493,40.535 12.465,40.535 v1(12.925,40.075)
  Bottom Layer w0.12: v1(-8.875,41.85) -9.51,41.215 -9.51,21.384 -9.345,21.219 -9.345,13.972 -8.85,13.477 -8.85,3.77 CN5.35@-7.62,2.54 ; v1(12.925,40.075) 14.49,38.51 16.312,38.51 18.285,36.537 18.285,35.604 19.405,34.484 19.405,33.338 18.967,32.9 SB22.2@16.475,32.9 16.6,32.775 16.6,31.725
PB5: CN6.29 CN9.5 SB26.2 SB27.2 | length 65.8
  Top Layer w0.12: v1(18.276,30.576) 20.375,30.576 22.78,32.982 40.663,32.982 40.895,32.75 42.302,32.75 42.702,33.15 43.225,33.15 43.225,33.225 v1(43.227,33.227) ; v1(43.55,10.16) CN9.5@48.26,10.16 49.245,9.175 52.355,9.175 CN6.29@53.34,10.16
  Bottom Layer w0.12: 16.8,30.3 16.8,28.8 17.3,28.8 18.263,29.763 18.263,30.563 v1(18.276,30.576) ; v1(43.227,33.227) 43.227,32.388 44.075,31.54 44.075,29.525 43.792,29.242 43.792,28.633 44.68,27.746 44.68,23.411 44,22.731 44,19.626 43.665,19.291 43.665,15.891 43.09,15.316 43.09,10.62 v1(43.55,10.16)
PB6: CN6.21 CN7.1 SB28.2 SB36.2 | length 54.7
  Top Layer w0.12: v1(18.773,31.425) 18.775,31.425 19.223,31.873 20.314,31.873 22.383,33.942 41.408,33.942 v1(41.45,33.9) ; v1(42.8,21.65) 48.066,21.65 CN7.1@48.26,21.844 49.784,20.32 CN6.21@53.34,20.32
  Bottom Layer w0.12: SB36.2@16.475,26.15 16.955,26.63 16.955,27.836 ; SB28.2@16.475,27.5 16.63,27.5 16.63,27.511 16.955,27.836 ; v1(18.773,31.425) 18.773,29.654 16.955,27.836 ; v1(41.45,33.9) 41.45,33.328 42.142,32.636 42.142,28.308 42.8,27.65 v1(42.8,21.65)
PB7: CN6.5 CN7.9 SB38.2 SB41.1 | length 51.8
  Top Layer w0.12: v1(19.265,31.036) 19.782,31.553 20.447,31.553 22.515,33.622 40.928,33.622 41.16,33.39 41.591,33.39 41.91,33.709 41.91,33.714 42.125,33.929 v1(42.102,33.952) ; v1(44.775,42.1) 48.196,42.1 CN7.9@48.26,42.164 49.786,42.164 51.31,40.64 CN6.5@53.34,40.64
  Bottom Layer w0.12: SB41.1@16.925,23.45 16.925,24.7 SB38.2@17.025,24.8 17.755,24.8 17.905,24.95 17.905,28.235 19.325,29.655 19.325,30.976 v1(19.265,31.036) ; v1(42.102,33.952) 42.152,33.952 42.775,34.575 42.775,37.808 44.775,39.808 v1(44.775,42.1)
PB8: CN6.3 CN7.10 SB53.2 SB55.2 | length 59.8
  Top Layer w0.12: v1(20.201,31.077) 20.201,31.049 20.395,31.049 22.648,33.302 40.796,33.302 41.027,33.07 41.995,33.07 42.175,33.25 42.175,33.254 v1(42.152,33.277) ; v1(45.225,44.7) 45.721,44.7 45.725,44.704 CN7.10@48.26,44.704 51.446,44.704 52.97,43.18 CN6.3@53.34,43.18
  Bottom Layer w0.12: SB55.2@19.3,18.025 SB53.2@19.3,19.375 20.052,19.375 20.225,19.547 20.225,21.382 18.69,22.917 18.69,28.115 19.33,28.755 19.335,28.755 19.965,29.385 19.965,29.39 20.223,29.648 20.223,31.077 v1(20.201,31.077) ; v1(42.152,33.277) 42.154,33.275 42.154,33.331 43.095,34.273 43.095,37.675 45.24,39.82 45.24,44.685 v1(45.225,44.7)
PB9: CN5.37 SB58.2 | length 45
  Top Layer w0.12: v1(-1.975,16.025) -1.975,15.975 -1.86,15.86 2.507,15.86 4.057,17.41 8.043,17.41 8.464,16.989 10.964,16.989 v1(11,17.025)
  Bottom Layer w0.12: CN5.37@-7.62,0 -7.15,0 -5.925,1.225 -4.375,1.225 -3.525,2.075 -3.525,10.42 -1.995,11.95 -1.995,16.005 v1(-1.975,16.025) ; v1(11,17.025) 11.34,17.365 11.34,17.866 11.684,18.21 12.757,18.21 13.085,17.882 13.085,17.04 14.225,15.9 19.475,15.9 19.575,16 19.575,16.725
PB10: CN6.25 CN9.7 SB49.2 SB54.2 | length 22.5
  Top Layer w0.12: v1(37.175,17.9) 38.277,17.9 39.002,17.175 43.377,17.175 45.312,15.24 CN9.7@48.26,15.24 48.26,14.828 49.738,13.35 51.849,13.35 53.34,14.841 CN6.25@53.34,15.24
  Bottom Layer w0.12: SB49.2@36.05,20.625 SB54.2@36.05,19.225 36.057,19.225 37.175,18.107 v1(37.175,17.9)
PB11: CN6.16 SB37.2 | length 20.6
  Top Layer w0.127: v1(41.827,23.201) 41.878,23.15 51.375,23.15 v1(51.775,23.55)
  Bottom Layer w0.12: SB37.2@40.7,25.575 41.475,25.575
  Bottom Layer w0.127: 41.475,25.575 41.801,25.249 41.801,23.175 v1(41.827,23.201) ; v1(51.775,23.55) 52.325,24.1 54.075,24.1 54.625,24.65 54.625,26.275 55.88,27.53 CN6.16@55.88,27.94
PB12: CN5.13 U9.33 | length 42.4
  Top Layer w0.12: CN5.13@-7.62,30.48 -6.365,29.225 4.5,29.225 5.05,29.775 20.479,29.775 22.904,32.2 v1(25.6,32.2) ; U9.33@25.34,24.95 25.34,26.415 25.65,26.725 25.624,26.751 v1(25.601,26.751)
  Bottom Layer w0.12: v1(25.6,32.2) 25.601,32.199 v1(25.601,26.751)
PB13: CN6.11 CN7.6 SB17.1 U9.34 | length 47.5
  Top Layer w0.12: U9.34@24.84,24.95 24.84,26.684 25.4,27.244 46.904,27.244 47.769,28.109 48.891,28.109 49.756,27.244 51.949,27.244 52.568,26.625 v1(54.275,26.625) ; CN7.6@48.26,34.544 51.231,34.544 52.755,33.02 CN6.11@53.34,33.02
  Bottom Layer w0.12: CN6.11@53.34,33.02 54.575,31.785 54.575,26.925 v1(54.275,26.625)
  Bottom Layer w0.4: SB17.1@46.425,35.975 46.829,35.975 CN7.6@48.26,34.544
PB14: CN6.13 CN7.5 U9.35 | length 35.4
  Top Layer w0.12: U9.35@24.34,24.95 24.34,26.637 25.267,27.564 46.772,27.564 47.225,28.017 v1(47.225,28.275) ; CN7.5@48.26,32.004 49.621,32.004 51.145,30.48 CN6.13@53.34,30.48
  Bottom Layer w0.12: v1(47.225,28.275) 47.075,28.425 47.075,30.819 CN7.5@48.26,32.004
PB15: CN6.15 CN7.4 U9.36 | length 33
  Top Layer w0.12: U9.36@23.84,24.95 23.84,26.589 25.135,27.884 45.525,27.884 47.105,29.464 CN7.4@48.26,29.464 49.436,29.464 50.96,27.94 CN6.15@53.34,27.94
PC0: CN5.38 CN10.6 U9.8 | length 49.3
  Top Layer w0.12: CN5.38@-5.08,0 CN10.6@0,0 1.81,-1.81 25.94,-1.81 26.125,-1.625 26.125,-1.671 v1(26.11,-1.686) ; U9.8@21.34,13.15 21.34,11.899 24.223,9.016 24.223,8.225 v1(24.211,8.213)
  Bottom Layer w0.12: v1(24.211,8.213) 24.211,7.389 26.305,5.295 26.305,0.442 26.49,0.257 26.49,-1.433 26.238,-1.686 v1(26.11,-1.686)
PC1: CN5.36 CN10.5 U9.9 | length 50.3
  Top Layer w0.12: CN5.36@-5.08,2.54 CN10.5@0,2.54 1.432,2.54 5.142,-1.17 25.523,-1.17 25.837,-0.856 26.454,-0.856 26.813,-1.215 v1(26.95,-1.215) ; U9.9@21.84,13.15 21.84,11.922 24.605,9.157 24.605,8.47 24.7,8.375 v1(24.7,7.75)
  Bottom Layer w0.12: v1(24.7,7.75) 24.7,7.375 26.625,5.45 26.625,0.575 26.95,0.25 v1(26.95,-1.215)
PC2: CN5.34 CN10.4 U9.10 | length 53.4
  Top Layer w0.12: CN5.34@-5.08,5.08 CN10.4@0,5.08 1.275,3.805 1.275,3.15 5.275,-0.85 25.391,-0.85 25.755,-0.486 26.936,-0.486 27.015,-0.565 27.015,-0.582 27.633,-1.2 v1(28.05,-1.2) ; U9.10@22.34,13.15 22.34,11.946 24.975,9.311 24.975,8.644 25.16,8.459 25.16,7.525 25.15,7.515 25.44,7.225 25.44,7.239 v1(25.476,7.275)
  Bottom Layer w0.12: v1(25.476,7.275) 25.476,7.052 26.945,5.583 26.945,1.855 26.95,1.85 26.95,1.125 28.21,-0.135 28.21,-1.04 v1@28.063,-1.187 ; v1@28.063,-1.188 28.075,-1.2 v1(28.05,-1.2) v1@28.063,-1.187
PC3: CN5.32 CN10.3 U9.11 | length 66.4
  Top Layer w0.12: v1(-6.725,1.25) 0.527,1.25 3.267,-1.49 25.656,-1.49 25.92,-1.226 26.301,-1.226 26.508,-1.433 26.75,-1.675 28.55,-1.675 v1(28.575,-1.65) ; CN5.32@-5.08,7.62 CN5.32@-4.86,7.4 ; CN5.32@-5.03,7.595 -1.405,7.595 CN10.3@0.05,7.595 ; U9.11@22.84,13.15 22.84,11.969 25.345,9.464 25.345,8.727 25.48,8.592 25.48,8.045 26.05,7.475 26.05,7.05 26.95,6.15 v1(27.028,6.15)
  Bottom Layer w0.12: v1(-6.725,1.25) -6.4,1.575 -6.4,6.05 -5.08,7.37 CN5.32@-5.08,7.62 ; v1(27.028,6.15) 27.27,5.908 27.27,1.258 28.575,-0.047 v1(28.575,-1.65)
PC4: CN6.34 U9.24 | length 40.8
  Top Layer w0.12: U9.24@27.49,18.8 28.67,18.8 29.71,17.76 35.992,17.76 37.777,15.975 44.053,15.975 45.528,14.5 v1(46.477,14.501) ; v1(45.8,6.325) 45.825,6.35 48.9,6.35 49.925,5.325 51.525,5.325 52.55,6.35 54.61,6.35 CN6.34@55.88,5.08
  Bottom Layer w0.12: v1(45.8,6.325) 45.705,6.42 45.705,11.58 46.38,12.255 46.38,14.403 v1(46.477,14.501)
PC5: CN6.6 SB59.2 | length 40.6
  Top Layer w0.12: v1(45.7,40.875) 50.1,40.875 51.575,39.4 54.64,39.4 CN6.6@55.88,40.64
  Bottom Layer w0.12: SB59.2@40.7,15.325 41.742,15.325 42.315,15.898 42.315,18.846 43.36,19.891 43.36,22.996 44.04,23.676 44.04,27.48 43.15,28.37 43.15,29.825 42.767,30.208 42.767,33.492 43.415,34.14 43.415,37.543 45.7,39.828 v1(45.7,40.875)
PC6: CN6.4 U9.37 | length 49.9
  Top Layer w0.12: U9.37@23.34,24.95 23.34,26.542 25.002,28.204 41.304,28.204 41.5,28.4 41.499,28.401 v1(41.452,28.401) ; v1(44.3,43.4) 49.35,43.4 49.4,43.45 50.925,41.925 54.625,41.925 CN6.4@55.88,43.18
  Bottom Layer w0.12: v1(41.452,28.401) 41.475,28.424 41.475,32.851 40.99,33.336 40.99,34.091 42.4,35.501 42.4,37.95 44.3,39.85 v1(44.3,43.4)
PC7: CN6.23 CN9.8 U9.38 | length 45.1
  Top Layer w0.12: U9.38@22.84,24.95 22.84,26.494 24.87,28.524 40.737,28.524 41.123,28.91 41.64,28.91 42.346,28.204 45.079,28.204 45.226,28.351 v1(45.177,28.351) ; v1(44.775,17.775) 48.255,17.775 CN9.8@48.26,17.78 CN6.23@53.34,17.78
  Bottom Layer w0.12: v1(44.775,17.775) 45,18 45,21.724 44.64,22.084 44.64,22.466 45.32,23.146 45.32,28.209 v1(45.177,28.351)
PC8: CN6.2 U9.39 | length 54.6
  Top Layer w0.12: U9.39@22.34,24.95 22.34,26.447 24.737,28.844 40.605,28.844 40.991,29.23 41.773,29.23 42.479,28.524 44.624,28.524 45.1,29 v1(45.175,29) ; v1(46.75,46.25) 46.759,46.259 51.484,46.259 52.35,47.125 54.475,47.125 CN6.2@55.88,45.72
  Bottom Layer w0.12: v1(45.175,29) 45.175,31.797 44.375,32.597 44.375,36.55 46.75,38.925 v1(46.75,46.25)
PC9: CN6.1 U9.40 | length 50.6
  Top Layer w0.12: U9.40@21.84,24.95 21.84,26.399 24.611,29.17 40.478,29.17 40.858,29.55 41.905,29.55 42.611,28.844 44.125,28.844 ; v1(46.225,45.4) 47.125,45.4 47.614,45.889 53.34,45.889 CN6.1@53.34,45.72
  Bottom Layer w0.12: v1(44.252,29.001) 44.395,29.144 44.395,31.672 43.735,32.332 43.735,37.41 46.225,39.9 v1(46.225,45.4)
PC10: CN5.1 U9.51 | length 52.8
  Top Layer w0.12: CN5.1@-7.62,45.72 -6.115,47.225 -4.413,47.225 -3.692,46.504 8.959,46.504 9.875,47.42 12.433,47.42 12.75,47.102 v1(13.101,47.102)
  Top Layer w0.127: v1(12.251,21.351) v1(12.251,21.351) 12.125,21.35 12.575,21.8 U9.51@15.69,21.8
  Bottom Layer w0.12: v1(12.251,21.351) 12.16,21.442 12.16,38.59 11.491,39.259 11.491,41.623 12.16,42.292 12.16,46.162 v1(13.101,47.102)
PC11: CN5.2 U9.52 | length 46.2
  Top Layer w0.127: CN5.2@-5.08,45.72 -5.08,45.86 8.79,45.86 10.488,44.162 12.787,44.162 v1(12.8,44.175) ; v1(13,20.65) 13,20.78 13.483,21.263 15.653,21.263 U9.52@15.69,21.3
  Bottom Layer w0.127: v1(12.8,44.175) 12.483,43.858 12.483,42.158 11.815,41.489 11.815,39.393 12.483,38.724 12.483,21.774 13,21.257 v1(13,20.65)
PC12: CN5.3 U9.53 | length 52.9
  Top Layer w0.12: CN5.3@-7.62,43.18 -6.265,44.535 -6.265,46.211 -5.571,46.905 -4.546,46.905 -3.825,46.184 9.091,46.184 10.007,47.1 12.3,47.1 12.8,46.6 v1(12.8,45.875)
  Top Layer w0.127: v1(13.675,20.8) U9.53@15.69,20.8
  Bottom Layer w0.12: v1(12.8,45.875) 12.8,44.875 13.26,44.415 13.26,43.984 12.807,43.531 12.807,42.024 12.138,41.355 12.138,39.527 12.807,38.858 12.807,21.938 13.675,21.07 v1(13.675,20.8)
PC13: CN5.23 SB50.2 U9.2 | length 36.8
  Top Layer w0.12: CN5.23@-7.62,17.78 -6.185,16.345 -4.175,16.345 -3.13,15.3 2.775,15.3 4.325,16.85 7.811,16.85 8.356,16.305 11.399,16.305 11.7,16.004 11.7,15 12.475,14.225 14.525,14.225 14.8,14.5 ; 15,14.5 14.8,14.5 ; U9.2@18.34,13.15 18.34,14.21 18.05,14.5 14.8,14.5
  Bottom Layer w0.12: CN5.23@-7.62,17.78 -7.62,18.43 -6.7,19.35 -6,19.35 -5.675,19.025 -4.475,19.025 -3.5,20 SB50.2@-3.2,20
PC14: CN5.25 SB72.1 | length 32.3
  Top Layer w0.12: v1(-6.375,18.8) -6.21,18.965 6.307,18.965 6.787,18.485 8.464,18.485 8.759,18.19 v1(9.41,18.19)
  Bottom Layer w0.12: CN5.25@-7.62,15.24 -6.35,16.51 -6.35,18.775 v1(-6.375,18.8) ; v1(9.41,18.19) 9.84,17.76 9.84,16.393 11.925,14.308 11.925,13.167 11.84,13.082 11.84,12.618 12.333,12.125 14.847,12.125 16.047,10.925 SB72.1@16.525,10.925
PC15: CN5.27 SB71.1 | length 44.7
  Top Layer w0.12: v1(-9.05,21.575) 4.15,21.575 6.92,18.805 8.795,18.805 v1(8.95,18.65)
  Bottom Layer w0.12: v1(-9.05,21.575) -9.025,21.55 -9.025,14.105 CN5.27@-7.62,12.7 ; v1(8.95,18.65) 8.95,16.76 10.815,14.895 10.82,14.895 11.555,14.16 11.555,13.32 11.47,13.235 11.47,12.465 12.185,11.75 14.77,11.75 15.815,10.704 15.815,10.138 16.028,9.925 17.705,9.925 17.925,10.145 SB71.1@17.925,10.925
PD2: CN5.4 SB16.2 | length 30.5
  Top Layer w0.127: CN5.4@-5.076,43.176 CN5.4@-5.08,43.18 -5.08,43.945 -3.492,45.533 8.654,45.533 10.476,43.712 13.089,43.712 v1(13.425,43.375)
  Bottom Layer w0.127: v1(13.425,43.375) 13.13,43.08 13.13,41.89 12.462,41.221 12.462,39.863 14.138,38.187 16.163,38.187 16.475,37.875 SB16.2@16.475,36.95
PH0: CN5.29 SB70.1 | length 50.7
  Top Layer w0.12: CN5.29@-7.62,10.16 -6.435,11.345 v1@-1.425,11.345 ; v1(6.775,2.525) 6.775,-0.325 6.98,-0.53 19.521,-0.53 v1(19.676,-0.375)
  Bottom Layer w0.12: v1(-1.425,11.35) -1.675,11.1 -1.675,7.45 -0.6,6.375 3.215,6.375 6.775,2.815 v1(6.775,2.525) ; SB70.1@19.325,10.925 19.325,10.15 20.845,8.63 20.845,5.615 21.565,4.895 21.565,2.49 20.745,1.67 20.35,1.67 19.915,1.235 19.915,-0.285 19.7,-0.5 19.676,-0.476 v1(19.676,-0.375)
PH1: CN5.31 SB68.1 | length 45.8
  Top Layer w0.12: CN5.31@-7.62,7.62 -6.4,6.4 0.7,6.4 3.225,8.925 5.881,8.925 ; 5.881,8.925 v1(6.625,8.925) ; v1(13.225,4.575) 13.155,4.505 13.155,1.84 13.525,1.47 17.564,1.47 18.08,1.985 18.08,1.992 18.698,2.61 21.91,2.61 v1(22.025,2.725)
  Bottom Layer w0.12: v1(6.625,8.925) 6.711,8.925 6.715,8.921 8.775,6.86 11.541,6.86 13.225,5.176 v1(13.225,4.575) ; v1(22.025,2.725) 22.025,4.958 21.215,5.768 21.215,6.232 22.125,7.142 SB68.1@22.125,10.925
PWR_ENN: R25.2 U2.28 U4.4 | length 23.5
  Top Layer w0.25: U2.28@28.38,60.98 30.27,60.98 30.675,60.575 33.025,60.575 33.405,60.195 33.405,59.845 33.595,59.655 36.12,59.655 36.825,58.95 v1(41.475,58.95)
  Top Layer w0.4: v1(42.2,55.95) 42.225,55.975 R25.2@43.675,55.975 43.68,55.98 45.455,55.98 46.875,57.4 U4.4@47.7,57.4
  Bottom Layer w0.4: v1(41.475,58.95) 41.475,57.174 42.2,56.449 v1(42.2,55.95)
SMPS_EN: CN11.5 SB84.1 SB92.1 U12.12 | length 23.6
  Top Layer w0.12: U12.12@14.575,8.875 14.9,8.875 15.035,8.74 15.035,6.44 v1(14.945,6.35) ; v1(14.725,4.725) 14.69,4.725 13.475,3.51 13.475,2.165 13.85,1.79 17.432,1.79 17.76,2.118 17.76,2.124 18.711,3.075 v1(19.15,3.075)
  Bottom Layer w0.12: v1(14.725,4.725) 14.945,4.945 v1(14.945,6.35) ; CN11.5@19.05,-3 18.7,-2.65 SB92.1@18.7,-0.675 18.075,-0.675 17.925,-0.525 17.925,1.5 18.467,2.042 19.675,2.042 20.05,2.417 SB84.1@20.05,3.125 19.15,3.125 v1(19.15,3.075)
SMPS_PG: CN11.7 R40.1 SB93.1 U11.C1 U12.7 | length 30.5
  Top Layer w0.12: U11.C1@6.775,12.05 7.407,12.05 ; R40.1@7.7,13.85 7.7,12.343 7.407,12.05 ; v1(13,7.4) U12.7@13,8.2 ; v1(14.976,10.251) 15.06,10.335 15.06,11.007 14.732,11.335 14.268,11.335 13.898,10.965 8.492,10.965 7.84,11.617 7.407,12.05
  Bottom Layer w0.12: v1(13,7.4) 13.196,7.4 14.611,8.814 ; CN11.7@13.97,-3 14.65,-2.32 14.65,-0.875 13.975,-0.875 13.9,-0.8 13.9,1.198 14.785,2.083 14.785,3.885 15.925,5.025 15.925,7.5 14.611,8.814 ; v1(14.976,10.251) 14.611,9.886 14.611,8.814
SMPS_SW: CN11.6 R38.2 SB88.1 U12.1 | length 35.3
  Top Layer w0.12: R38.2@6.4,22.3 7.725,22.3 v1(7.85,22.175) ; v1(11.225,11.425) 13.905,11.425 14.135,11.655 14.865,11.655 15.495,11.025 15.495,9.72 v1(15.15,9.375) 14.975,9.55 U12.1@14.6,9.55
  Bottom Layer w0.12: v1(7.85,22.175) 7.85,17.337 10.662,14.525 10.667,14.525 11.185,14.007 11.185,13.473 11.1,13.388 11.1,12.312 11.225,12.187 v1(11.225,11.425) ; v1(15.15,9.375) 15.1,9.325 15.1,8.876 15.276,8.7 15.278,8.7 16.375,7.603 16.375,4.125 15.55,3.3 15.55,-0.7 15.75,-0.9 16.125,-0.9 16.475,-0.55 ; SB88.1@16.375,-0.675 16.375,-2.865 CN11.6@16.51,-3
SMPS_V1: CN11.4 SB89.1 SB90.1 SB91.1 | length 5.1
  Bottom Layer w0.12: SB91.1@20.625,-0.675 SB90.1@21.95,-0.675 ; CN11.4@21.59,-3 21.95,-2.64 SB90.1@21.95,-0.675 ; SB89.1@23.275,-0.675 SB90.1@21.95,-0.675
STLINK_RX: CN4.1 SB32.1 SB75.1 U2.12 | length 124.4
  Top Layer w0.12: CN4.1@1.27,58.42 1.288,58.42 3.185,60.317 3.185,60.503 4.757,62.075 9.268,62.075 11.891,59.452 16.8,59.452 17.352,58.9 17.575,58.9 17.85,58.625 19.375,58.625 v1(19.628,58.878) 19.88,59.13 U2.12@19.88,59.48 ; v1(21.601,29.175) 21.601,29.399 22.973,30.77 38.67,30.77 v1(38.85,30.95) 39.995,30.95 40.195,31.15 42.775,31.15 v1(43.275,31.65)
  Bottom Layer w0.12: v1(19.628,58.878) 19.628,59.323 20.764,60.46 21.99,60.46 22.6,59.85 22.6,55.242 22.165,54.807 22.165,54.343 22.493,54.015 29.225,54.015 30.09,53.15 30.09,51.664 31.804,49.95 40.615,49.95 41.44,49.125 41.44,35.898 38.85,33.308 v1(38.85,30.95) ; v1(21.601,29.175) 21.625,29.151 21.625,26.15 ; 40.575,10.075 41.025,10.075 ; SB75.1@40.6,9.85 41.825,9.85 42.77,10.795 42.77,15.448 43.345,16.023 43.345,19.423 43.68,19.758 43.68,22.863 44.36,23.543 44.36,27.613 43.472,28.501 43.472,29.15 ; v1(43.275,31.65) 43.47,31.455 43.47,29.15
STLINK_TX: SB12.2 SB34.1 SB66.1 U5.6 | length 62.7
  Top Layer w0.12: U5.6@15.45,55.525 16.225,55.525 v1(16.425,55.325) ; v1(16.426,53.953) 16.426,53.974 16.935,53.465 27.8,53.465 29.15,52.115 29.15,45.95 30.125,44.975 30.125,42.925 29.535,42.335 28.64,42.335 v1(28.475,42.5)
  Bottom Layer w0.12: SB12.2@16.4,56.25 16.425,56.225 v1(16.425,55.325) v1@16.425,53.953 ; 26.15,12.8 25.775,12.8 25.45,13.125 25.45,15.533 25.685,15.768 25.685,16.39 25.375,16.7 25.375,18.4 24.715,19.06 24.715,22.96 25.3,23.545 25.3,26.175 24.925,26.55 24.425,26.55 24.425,31.875 25.21,32.66 26.86,32.66 28.475,34.275 v1(28.475,42.5)
STLINK_USB_D_N: CN1.2 U1.1 U1.6 U2.32 | length 18.4
  Top Layer w0.12: U2.32@28.38,62.98 29.04,62.98 29.105,63.045 30.228,63.045 30.633,63.45 33.975,63.45 35.245,64.72 35.245,65.395 35.775,65.925 37.275,65.925 37.55,66.2 37.55,66.938 37.06,67.428 37.06,68.71 U1.6@37,68.77 U1.1@37,70.38 37,71.258 37.06,71.318 37.06,71.782 36.845,71.997 CN1.2@36.845,73.31
STLINK_USB_D_P: CN1.3 R12.2 U1.3 U1.4 U2.33 | length 17.4
  Top Layer w0.12: U2.33@28.38,63.48 29.04,63.48 29.105,63.415 30.075,63.415 30.48,63.82 33.822,63.82 34.875,64.873 34.875,65.548 35.622,66.295 36.395,66.295 R12.2@36.7,66.6 36.475,66.6 35.94,67.135 35.94,68.04 36,68.1 U1.4@36,68.77 U1.3@36,70.38 36,71.258 35.94,71.318 35.94,71.782 36.195,72.037 CN1.3@36.195,73.31
STLK_OSC_IN: C7.1 U2.5 X1.2 | length 7.3
  Top Layer w0.127: C7.1@13.075,64.25 14.625,64.25 X1.2@15.175,63.7 17.2,63.7 17.92,62.98 U2.5@19.88,62.98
